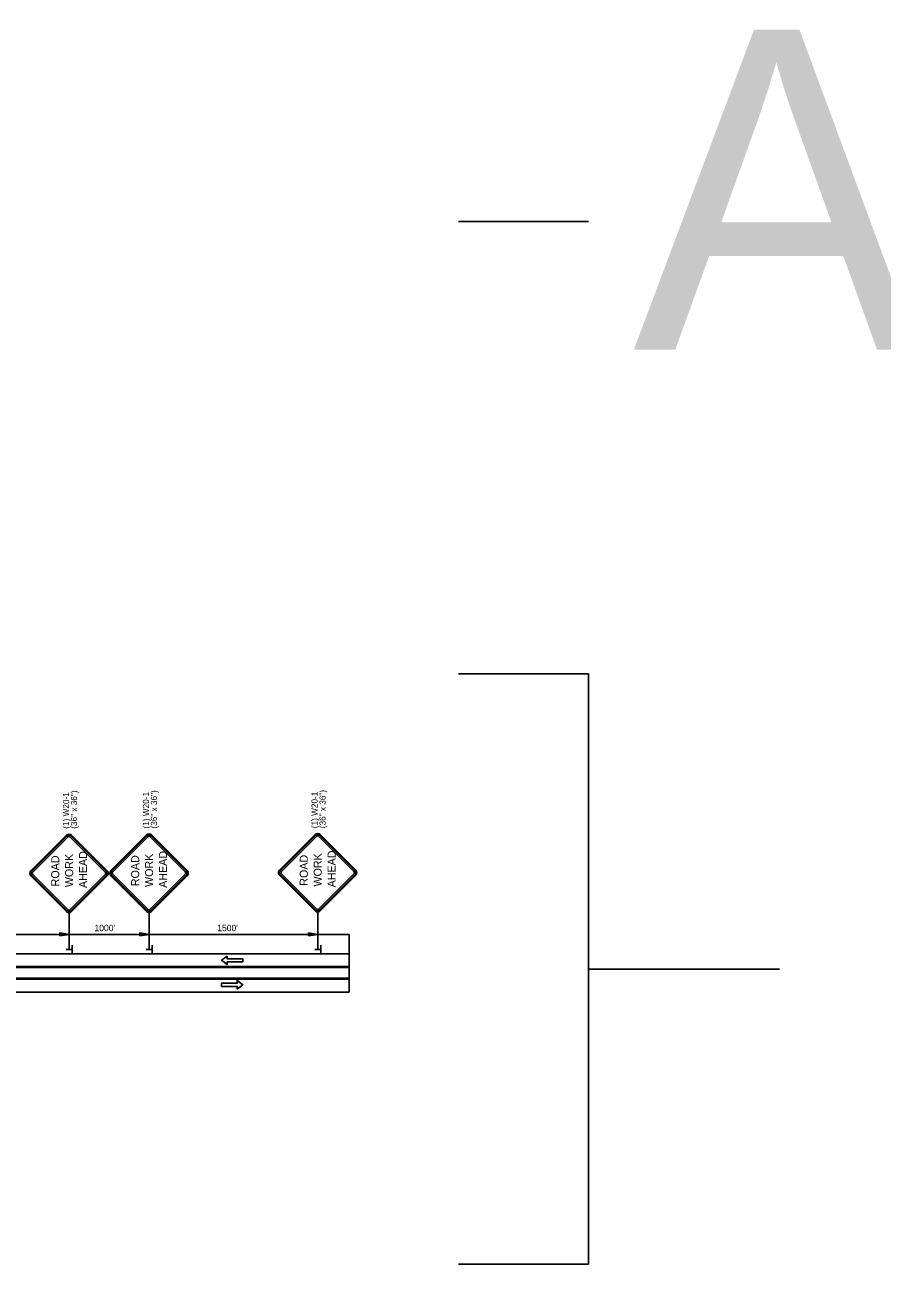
# Model space of a CAD drawing. Extents: x 1930579 to 1946213, y 596452 to 597784.
# Drawn here: x 1939196 to 1940000, y 596622 to 597784 of the extents above; entities that cross this region are included whole.
import ezdxf

# ---------------------------------------------------------------- set-up
doc = ezdxf.new("R2010")
doc.units = 0
for name, color, linetype in [('Default', 7, 'Continuous'), ('P_TC_Signs_Temporary', 7, 'Continuous'), ('R_Border', 7, 'Continuous'), ('R_Striping', 7, 'Continuous')]:
    doc.layers.add(name, color=color, linetype=linetype)

# ---------------------------------------------------------------- blocks, each defined once
blk = doc.blocks.new('W20-1')
at = {"layer": 'P_TC_Signs_Temporary'}
for p, q in [((-5.97, 6.53), (-0.4, 12.1)), ((-5.86, 6.42), (-0.29, 11.99)), ((-5.7, 6.26), (-0.13, 11.83)), ((0.13, 11.83), (5.7, 6.26)), ((0.29, 11.99), (5.86, 6.42)), ((0.4, 12.1), (5.97, 6.53)), ((-0.29, 0.28), (-5.86, 5.84)), ((-0.13, 0.43), (-5.7, 6)), ((5.7, 6), (0.13, 0.43)), ((5.86, 5.84), (0.29, 0.28)), ((-0.4, 0.16), (-5.97, 5.73)), ((5.97, 5.73), (0.4, 0.16))]:
    blk.add_line(p, q, dxfattribs=at)
for centre, radius, start, end in [((0, 11.7), 0.562, 45, 135), ((0, 11.7), 0.406, 45, 135), ((0, 11.7), 0.188, 45, 135), ((-5.57, 6.13), 0.562, 135, 225), ((-5.57, 6.13), 0.406, 135, 225), ((-5.57, 6.13), 0.187, 135, 225), ((5.57, 6.13), 0.187, 315, 45), ((5.57, 6.13), 0.406, 315, 45), ((5.57, 6.13), 0.562, 315, 45), ((0, 0.56), 0.562, 225, 315), ((0, 0.56), 0.406, 225, 315), ((0, 0.56), 0.188, 225, 315)]:
    blk.add_arc(centre, radius, start, end, dxfattribs=at)
for s, p in [(' ROAD ', (-2.5, 7.67)), ('WORK', (-2.16, 5.5)), (' AHEAD ', (-2.76, 3.33))]:
    blk.add_text(s, height=1.25, dxfattribs=at).set_placement(p)

msp = doc.modelspace()

# ---------------------------------------------------------------- linework, layer by layer
at = {"layer": 'Default'}
for p, q in [((1939602.7, 597599.6), (1939724.7, 597599.6)), ((1939602.7, 597175.5), (1939724.7, 597175.5)), ((1939724.7, 597175.5), (1939724.7, 596622.3)), ((1939500.2, 596931.4), (1939146.1, 596931.4)), ((1939229.2, 596930), (1939229.2, 596932.7)), ((1939229.2, 596932.7), (1939238.1, 596931.4)), ((1939238.1, 596931.4), (1939229.2, 596930)), ((1939304.1, 596930), (1939304.1, 596932.7)), ((1939304.1, 596932.7), (1939313, 596931.4)), ((1939313, 596931.4), (1939304.1, 596930)), ((1939462.1, 596930), (1939462.1, 596932.7)), ((1939462.1, 596932.7), (1939471, 596931.4)), ((1939471, 596931.4), (1939462.1, 596930)), ((1939500.2, 596931.4), (1939500.2, 596877.3)), ((1939240.7, 596917.3), (1939235.2, 596917.3)), ((1939240.8, 596921.3), (1939240.8, 596913.3)), ((1939315.6, 596917.3), (1939310.2, 596917.3)), ((1939315.7, 596921.3), (1939315.7, 596913.3)), ((1939473.5, 596917.3), (1939468.1, 596917.3)), ((1939473.7, 596921.3), (1939473.7, 596913.3)), ((1938472, 596913.3), (1939500.2, 596913.3)), ((1938472, 596901.3), (1939500.2, 596901.3)), ((1938472, 596900.3), (1939500.2, 596900.3)), ((1938472, 596890.3), (1939500.2, 596890.3)), ((1939724.7, 596898.9), (1939903.6, 596898.9)), ((1938472, 596889.3), (1939500.2, 596889.3)), ((1938472, 596877.3), (1939500.2, 596877.3)), ((1939602.7, 596622.3), (1939724.7, 596622.3))]:
    msp.add_line(p, q, dxfattribs=at)
at = {"layer": 'R_Border'}
for p, q in [((1939237.9, 596917.3), (1939237.9, 596951.9)), ((1939313, 596917.3), (1939313, 596951.9)), ((1939471.1, 596917.3), (1939471, 596951.9))]:
    msp.add_line(p, q, dxfattribs=at)
at = {"layer": 'R_Striping'}
for points in [[(1939386, 596911.1), (1939380.8, 596907.1), (1939386, 596903.1), (1939386, 596905.6), (1939400.7, 596905.6), (1939400.7, 596908.6), (1939386, 596908.6)], [(1939395.5, 596880.2), (1939400.7, 596884.2), (1939395.5, 596888.2), (1939395.5, 596885.7), (1939380.8, 596885.7), (1939380.8, 596882.7), (1939395.5, 596882.7)]]:
    msp.add_lwpolyline(points, close=True, dxfattribs=at)

# ---------------------------------------------------------------- block references
at = {"layer": 'Default', "xscale": 6, "yscale": 6, "rotation": 89.99999999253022}
for p in [(1939274.7, 596988.6), (1939349.6, 596988.8), (1939507.6, 596989.2)]:
    msp.add_blockref('W20-1', p, dxfattribs=at)

# ---------------------------------------------------------------- texts
at = {"layer": 'Default'}
for s, height, p in [('APPROACHING THE WORK ZONE', 300, (1939766.3, 597479.3)), ("1000'", 6, (1939261.7, 596934.4)), ("1500'", 6, (1939376.7, 596934.4))]:
    msp.add_text(s, height=height, rotation=360, dxfattribs=at).set_placement(p)
at = {"layer": 'R_Border'}
for s, p in [('(36" x 36")', (1939245.4, 597030.4)), ('(1) W20-1', (1939312.8, 597030.6)), ('(36" x 36")', (1939320.3, 597030.6)), ('(1) W20-1', (1939470.8, 597030.9)), ('(36" x 36")', (1939478.3, 597030.9)), ('(1) W20-1', (1939237.9, 597030.4))]:
    msp.add_text(s, height=5.76, rotation=90, dxfattribs=at).set_placement(p)

doc.saveas('drawing.dxf')
